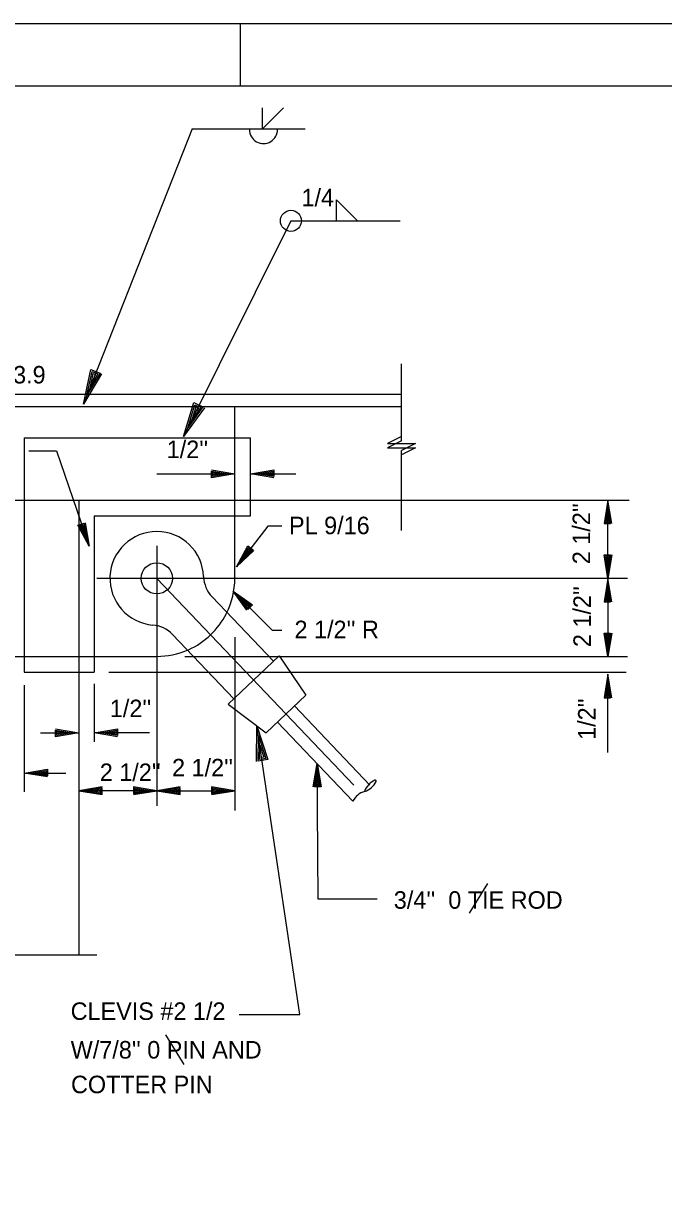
# Model space of a CAD drawing. Extents: x 0.1 to 13.5, y 0.1 to 9.5.
# Drawn here: x 7.629 to 9.337, y 6.319 to 9.458 of the extents above; entities that cross this region are included whole.
import ezdxf

# ---------------------------------------------------------------- set-up
doc = ezdxf.new("R2010")
doc.units = 0
for name, color, linetype in [('Level 1', 7, 'Continuous'), ('Level 13', 7, 'Continuous'), ('Level 25', 7, 'Continuous'), ('Level 3', 7, 'Continuous'), ('Level 44', 7, 'Continuous'), ('Level 50', 7, 'Continuous')]:
    doc.layers.add(name, color=color, linetype=linetype)

msp = doc.modelspace()

# ---------------------------------------------------------------- linework, layer by layer
at = {"layer": 'Level 1'}
for p, q in [((8.2083, 9.2917), (8.2083, 9.4583)), ((7.9845, 8.2564), (8.1928, 8.2564)), ((8.2345, 8.2564), (8.3555, 8.2564)), ((8.6378, 8.1857), (9.2449, 8.1857)), ((9.2409, 7.9773), (7.8241, 7.9773)), ((8.0595, 7.769), (9.2409, 7.769)), ((7.8567, 7.7273), (9.2369, 7.7273)), ((7.6739, 7.5649), (7.7761, 7.5649)), ((7.9651, 7.5649), (7.8178, 7.5649)), ((7.6303, 7.4575), (7.7421, 7.4575)), ((7.9845, 7.4104), (7.7761, 7.4104)), ((7.9845, 7.4104), (8.1928, 7.4104)), ((8.8673, 7.1624), (8.8185, 7.0837)), ((7.4072, 6.9726), (7.8241, 6.9726)), ((8.0575, 6.6798), (8.0087, 6.7586))]:
    msp.add_line(p, q, dxfattribs=at)
for points in [[(0.125, 9.4583), (13.4583, 9.4583), (13.4583, 0.125), (0.125, 0.125)], [(0.625, 9.2917), (13.2917, 9.2917), (13.2917, 0.2917), (0.625, 0.2917)]]:
    msp.add_lwpolyline(points, close=True, dxfattribs=at)
at = {"layer": 'Level 13'}
for points in [[(8.6378, 8.3559), (8.6003, 8.3372), (8.6752, 8.3372), (8.6378, 8.3185)], [(8.6378, 8.3442), (8.6003, 8.3256), (8.6752, 8.3256), (8.6378, 8.3068)]]:
    msp.add_lwpolyline(points, dxfattribs=at)
for centre, radius, start, end in [((8.5539, 7.36), 0.051, 107.0106, 153.8095), ((8.587, 7.3915), 0.051, 113.4241, 160.2247), ((8.5242, 7.4575), 0.051, 287.0106, 333.8112), ((8.5677, 7.436), 0.0025, 333.8112, 113.4241)]:
    msp.add_arc(centre, radius, start, end, dxfattribs=at)
at = {"layer": 'Level 25'}
for p, q in [((8.2667, 9.177), (8.2667, 9.2332)), ((8.2667, 9.177), (8.3226, 9.2329)), ((8.0792, 9.177), (7.7885, 8.4423)), ((8.0792, 9.177), (8.3806, 9.177)), ((8.4638, 8.988), (8.5196, 8.9321)), ((8.4638, 8.9317), (8.4638, 8.988)), ((8.3425, 8.9317), (8.0561, 8.3558)), ((8.3425, 8.9317), (8.6337, 8.9317)), ((8.6378, 8.3442), (8.6378, 8.5502)), ((5.8356, 8.469), (8.6378, 8.469)), ((7.7981, 8.4664), (7.7981, 8.4664)), ((6.1774, 8.4357), (8.6378, 8.4357)), ((7.7885, 8.4423), (7.7885, 8.4423)), ((8.1928, 8.144), (8.1928, 8.4357)), ((7.6303, 8.3523), (7.6303, 7.7273)), ((7.6303, 8.3523), (8.2345, 8.3523)), ((8.0561, 8.3558), (8.0561, 8.3558)), ((8.0677, 8.3791), (8.0677, 8.3791)), ((8.2345, 8.1809), (8.2345, 8.3523)), ((8.6378, 8.1046), (8.6378, 8.3185)), ((8.6378, 8.1046), (8.6378, 8.3068)), ((6.7397, 8.1857), (8.6378, 8.1857)), ((7.7761, 8.1857), (7.7761, 6.9726)), ((7.7761, 8.1857), (8.2345, 8.1857)), ((8.2345, 8.144), (8.2345, 8.1809)), ((9.1885, 7.9773), (9.1885, 8.1857)), ((7.8178, 8.144), (8.2345, 8.144)), ((7.8178, 8.144), (7.8178, 7.7273)), ((8.1928, 7.9773), (8.1928, 8.144)), ((7.9845, 8.0638), (7.9845, 7.3701)), ((7.9845, 7.9773), (8.5102, 7.4256)), ((9.1885, 7.9773), (9.1885, 7.769)), ((8.1323, 7.9279), (8.2959, 7.7561)), ((8.0267, 7.8273), (8.1903, 7.6555)), ((8.1928, 7.8204), (8.1928, 7.3577)), ((7.547, 7.769), (7.8178, 7.769)), ((7.7761, 7.769), (7.9845, 7.769)), ((7.8178, 7.769), (7.8178, 7.769)), ((7.8178, 7.769), (7.9845, 7.769)), ((8.1752, 7.6412), (8.311, 7.7705)), ((8.311, 7.7705), (8.3821, 7.6656)), ((7.6303, 7.7273), (7.7761, 7.7273)), ((7.7761, 7.7273), (7.8178, 7.7273)), ((7.6303, 7.6924), (7.6303, 7.4073)), ((7.8178, 7.6955), (7.8178, 7.5405)), ((9.1885, 7.5128), (9.1885, 7.7211)), ((8.2765, 7.565), (8.3821, 7.6656)), ((8.1752, 7.6412), (8.2765, 7.565)), ((8.352, 7.6369), (8.5534, 7.4256)), ((8.3068, 7.5938), (8.5081, 7.3825))]:
    msp.add_line(p, q, dxfattribs=at)
for points in [[(7.8373, 8.5235), (7.7885, 8.4423), (7.8085, 8.5349), (7.8332, 8.5252), (7.7981, 8.4664), (7.8117, 8.5294), (7.8275, 8.5231), (7.8073, 8.4897), (7.8149, 8.5238), (7.8214, 8.5212), (7.8169, 8.5139)], [(8.1116, 8.4327), (8.0561, 8.3558), (8.0838, 8.4465), (8.1076, 8.4347), (8.0677, 8.3791), (8.0865, 8.4407), (8.1018, 8.4331), (8.0788, 8.4015), (8.0892, 8.4348), (8.0955, 8.4317), (8.0904, 8.4248)]]:
    msp.add_lwpolyline(points, dxfattribs=at)
for centre, radius in [((8.3425, 8.9317), 0.0281), ((7.9845, 7.9773), 0.0417)]:
    msp.add_circle(centre, radius, dxfattribs=at)
for centre, radius, start, end in [((8.2693, 9.1752), 0.0375, 180, 1.5792), ((7.9845, 7.9773), 0.125, 2.1999, 265.0192), ((8.1926, 7.9853), 0.0833, 182.1999, 223.6109), ((7.9845, 7.9773), 0.2083, 333.5287, 0), ((7.9845, 7.9773), 0.2083, 293.9464, 333.1723), ((7.9664, 7.7698), 0.0833, 43.6094, 85.0192), ((7.9845, 7.9773), 0.2083, 270, 293.2322)]:
    msp.add_arc(centre, radius, start, end, dxfattribs=at)
at = {"layer": 'Level 3'}
for p, q in [((7.7984, 8.0798), (7.7984, 8.0798)), ((7.804, 8.0634), (7.804, 8.0634)), ((8.1975, 8.0084), (8.1975, 8.0084)), ((8.2081, 8.0222), (8.2081, 8.0222)), ((8.1882, 7.9434), (8.1882, 7.9434)), ((8.2004, 7.9311), (8.2004, 7.9311)), ((8.4122, 7.4831), (8.4122, 7.4831)), ((8.4123, 7.4658), (8.4123, 7.4658))]:
    msp.add_line(p, q, dxfattribs=at)
for points in [[(7.6429, 8.3175), (7.7173, 8.3175), (7.804, 8.0634)], [(7.7937, 8.1258), (7.804, 8.0634), (7.7741, 8.1191), (7.7908, 8.1248), (7.7984, 8.0798), (7.7781, 8.1176), (7.7889, 8.1213), (7.7931, 8.0956), (7.7822, 8.1162), (7.7866, 8.1177), (7.7875, 8.112)], [(8.3183, 8.1169), (8.2811, 8.1169), (8.1975, 8.0084)], [(8.2437, 8.0515), (8.1975, 8.0084), (8.2274, 8.0641), (8.2414, 8.0533), (8.2081, 8.0222), (8.2284, 8.06), (8.2374, 8.0531), (8.2183, 8.0354), (8.2294, 8.0558), (8.2331, 8.053), (8.2288, 8.0491)], [(8.3183, 7.838), (8.2935, 7.838), (8.1882, 7.9434)], [(8.225, 7.892), (8.1882, 7.9434), (8.2396, 7.9066), (8.2271, 7.8941), (8.2004, 7.9311), (8.2353, 7.9061), (8.2273, 7.8981), (8.2122, 7.9193), (8.2311, 7.9057), (8.2278, 7.9024), (8.2245, 7.9071)], [(8.4023, 7.4207), (8.4122, 7.4831), (8.423, 7.4209), (8.4053, 7.4208), (8.4123, 7.4658), (8.4196, 7.4235), (8.4083, 7.4234), (8.4124, 7.4491), (8.4163, 7.4262), (8.4116, 7.4261), (8.4126, 7.4318)], [(8.5726, 7.1208), (8.4149, 7.1208), (8.4122, 7.4831)]]:
    msp.add_lwpolyline(points, dxfattribs=at)
at = {"layer": 'Level 44'}
for p, q in [((8.3663, 6.8133), (8.2518, 7.5836)), ((8.2046, 6.8133), (8.3663, 6.8133))]:
    msp.add_line(p, q, dxfattribs=at)
at = {"layer": 'Level 50'}
for p, q in [((8.1755, 8.2564), (8.1755, 8.2564)), ((8.1928, 8.2564), (8.1928, 8.2564)), ((8.2345, 8.2564), (8.2345, 8.2564)), ((8.2518, 8.2564), (8.2518, 8.2564)), ((9.1885, 8.1857), (9.1885, 8.1857)), ((9.1885, 8.1683), (9.1885, 8.1683)), ((9.1885, 7.9947), (9.1885, 7.9947)), ((9.1885, 7.9773), (9.1885, 7.9773)), ((9.1885, 7.9773), (9.1885, 7.9773)), ((9.1885, 7.96), (9.1885, 7.96)), ((9.1885, 7.7863), (9.1885, 7.7863)), ((9.1885, 7.769), (9.1885, 7.769)), ((9.1885, 7.7211), (9.1885, 7.7211)), ((9.1885, 7.7038), (9.1885, 7.7038)), ((8.2518, 7.5836), (8.2518, 7.5836)), ((7.7588, 7.5649), (7.7588, 7.5649)), ((7.7761, 7.5649), (7.7761, 7.5649)), ((7.8178, 7.5649), (7.8178, 7.5649)), ((7.8351, 7.5649), (7.8351, 7.5649)), ((8.2557, 7.5579), (8.2557, 7.5579)), ((7.6303, 7.4575), (7.6303, 7.4575)), ((7.6476, 7.4575), (7.6476, 7.4575)), ((7.7761, 7.4104), (7.7761, 7.4104)), ((7.7935, 7.4104), (7.7935, 7.4104)), ((7.9671, 7.4104), (7.9671, 7.4104)), ((7.9845, 7.4104), (7.9845, 7.4104)), ((7.9845, 7.4104), (7.9845, 7.4104)), ((8.0018, 7.4104), (8.0018, 7.4104)), ((8.1755, 7.4104), (8.1755, 7.4104)), ((8.1928, 7.4104), (8.1928, 7.4104))]:
    msp.add_line(p, q, dxfattribs=at)
for points in [[(8.1305, 8.2667), (8.1928, 8.2564), (8.1305, 8.246), (8.1305, 8.2637), (8.1755, 8.2564), (8.1331, 8.2494), (8.1331, 8.2607), (8.1588, 8.2564), (8.1358, 8.2527), (8.1358, 8.2574), (8.1415, 8.2564)], [(8.2968, 8.246), (8.2345, 8.2564), (8.2968, 8.2667), (8.2968, 8.249), (8.2518, 8.2564), (8.2941, 8.2634), (8.2941, 8.252), (8.2685, 8.2564), (8.2915, 8.26), (8.2915, 8.2554), (8.2858, 8.2564)], [(9.1988, 8.1233), (9.1885, 8.1857), (9.1782, 8.1233), (9.1958, 8.1233), (9.1885, 8.1683), (9.1815, 8.126), (9.1928, 8.126), (9.1885, 8.1517), (9.1848, 8.1287), (9.1895, 8.1287), (9.1885, 8.1343)], [(9.1988, 8.0397), (9.1885, 7.9773), (9.1782, 8.0397), (9.1958, 8.0397), (9.1885, 7.9947), (9.1815, 8.037), (9.1928, 8.037), (9.1885, 8.0113), (9.1848, 8.0343), (9.1895, 8.0343), (9.1885, 8.0287)], [(9.1988, 7.915), (9.1885, 7.9773), (9.1782, 7.915), (9.1958, 7.915), (9.1885, 7.96), (9.1815, 7.9177), (9.1928, 7.9177), (9.1885, 7.9433), (9.1848, 7.9203), (9.1895, 7.9203), (9.1885, 7.926)], [(9.1988, 7.8313), (9.1885, 7.769), (9.1782, 7.8313), (9.1958, 7.8313), (9.1885, 7.7863), (9.1815, 7.8287), (9.1928, 7.8287), (9.1885, 7.803), (9.1848, 7.826), (9.1895, 7.826), (9.1885, 7.8203)], [(9.1988, 7.6588), (9.1885, 7.7211), (9.1782, 7.6588), (9.1958, 7.6588), (9.1885, 7.7038), (9.1815, 7.6614), (9.1928, 7.6614), (9.1885, 7.6871), (9.1848, 7.6641), (9.1895, 7.6641), (9.1885, 7.6698)], [(7.7138, 7.5752), (7.7761, 7.5649), (7.7138, 7.5546), (7.7138, 7.5722), (7.7588, 7.5649), (7.7165, 7.5579), (7.7165, 7.5692), (7.7421, 7.5649), (7.7191, 7.5612), (7.7191, 7.5659), (7.7248, 7.5649)], [(7.8801, 7.5546), (7.8178, 7.5649), (7.8801, 7.5752), (7.8801, 7.5576), (7.8351, 7.5649), (7.8775, 7.5719), (7.8775, 7.5606), (7.8518, 7.5649), (7.8748, 7.5686), (7.8748, 7.5639), (7.8691, 7.5649)], [(8.2503, 7.4888), (8.2518, 7.5836), (8.2809, 7.4934), (8.2547, 7.4895), (8.2557, 7.5579), (8.2754, 7.4966), (8.2586, 7.4941), (8.2593, 7.5331), (8.2699, 7.4998), (8.2629, 7.4988), (8.2632, 7.5074)], [(7.6926, 7.4472), (7.6303, 7.4575), (7.6926, 7.4679), (7.6926, 7.4502), (7.6476, 7.4575), (7.69, 7.4645), (7.69, 7.4532), (7.6643, 7.4575), (7.6873, 7.4612), (7.6873, 7.4565), (7.6816, 7.4575)], [(7.8385, 7.4207), (7.7761, 7.4104), (7.8385, 7.4), (7.8385, 7.4177), (7.7935, 7.4104), (7.8358, 7.4034), (7.8358, 7.4147), (7.8101, 7.4104), (7.8331, 7.4067), (7.8331, 7.4114), (7.8275, 7.4104)], [(7.9221, 7.4), (7.9845, 7.4104), (7.9221, 7.4207), (7.9221, 7.403), (7.9671, 7.4104), (7.9248, 7.4174), (7.9248, 7.406), (7.9505, 7.4104), (7.9275, 7.414), (7.9275, 7.4094), (7.9331, 7.4104)], [(8.0468, 7.4207), (7.9845, 7.4104), (8.0468, 7.4), (8.0468, 7.4177), (8.0018, 7.4104), (8.0441, 7.4034), (8.0441, 7.4147), (8.0185, 7.4104), (8.0415, 7.4067), (8.0415, 7.4114), (8.0358, 7.4104)], [(8.1305, 7.4), (8.1928, 7.4104), (8.1305, 7.4207), (8.1305, 7.403), (8.1755, 7.4104), (8.1331, 7.4174), (8.1331, 7.406), (8.1588, 7.4104), (8.1358, 7.414), (8.1358, 7.4094), (8.1415, 7.4104)]]:
    msp.add_lwpolyline(points, dxfattribs=at)

# ---------------------------------------------------------------- texts
at = {"layer": 'Level 1'}
for p in [(9.141, 8.0151), (9.1431, 7.7938)]:
    msp.add_text("2 1/2''", height=0.0467, rotation=90, dxfattribs=at).set_placement(p)
for s, height, p in [('PL 9/16', 0.0467, (8.3374, 8.0952)), ("2 1/2'' R", 0.0467, (8.3521, 7.8176)), ("2 1/2''", 0.0467, (7.8324, 7.4364)), ("2 1/2''", 0.0467, (8.0253, 7.4488)), ("3/4''  0 TIE ROD", 0.046698, (8.6171, 7.0954)), ('CLEVIS #2 1/2', 0.046698, (7.7547, 6.7987)), ("W/7/8'' 0 PIN AND", 0.046698, (7.7548, 6.6956)), ('COTTER PIN', 0.0467, (7.7556, 6.603))]:
    msp.add_text(s, height=height, dxfattribs=at).set_placement(p)
at = {"layer": 'Level 25'}
for s, p in [('1/4', (8.3708, 8.9705)), ('C15 X 33.9', (7.3754, 8.4975)), ("1/2''", (8.011, 8.2983)), ("1/2''", (7.8592, 7.6068))]:
    msp.add_text(s, height=0.0467, dxfattribs=at).set_placement(p)
msp.add_text("1/2''", height=0.0467, rotation=90, dxfattribs=at).set_placement((9.1555, 7.5461))

doc.saveas('drawing.dxf')
